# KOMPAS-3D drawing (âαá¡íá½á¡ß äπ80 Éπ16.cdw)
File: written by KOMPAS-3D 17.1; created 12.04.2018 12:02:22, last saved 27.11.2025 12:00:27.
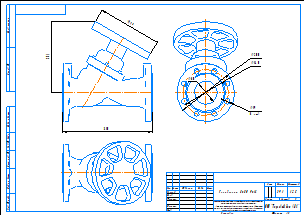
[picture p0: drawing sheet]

Sheet 1: A3, landscape

Title block, sheet 1: name: Гранбаланс Ду80 Ру16; material: Сталь 20  ГОСТ 1050-88; mass: 39,1; sheets: 1; sheet format: A3; stored path: C:\Users\kka\KOMPAS_Work\!Trash\КМ125 КМ127 КМ225Ф Двухходовые клапана\КМ125Ф + PSL\KOMPAS 2D\Гранрег КМ125Ф Ду32 Ру16.cdw

Views: Спереди 1, Спереди, Проекционный вид 2
Referenced files in C:\Users\mipv\Desktop\КБЧ\Имеющиеся\: Гранбаланс Ду80 Ру16  серия 10.m3d
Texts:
  kka
  adl
  Рама для чертежей
  Лит-Масса-Масштаб
  Материал-Предприятие
  Масштаб
  Изм.
  Лист
  № докум.
  Подп.
  Дата
  Лит.
  Разраб.
  Пров.
  Т.контр.
  Листов
  Внимание! Данный продукт является объектом авторского права ООО «Торговый Дом АДЛ».
  Запрещается изменение, копирование, распространение
  (в том числе путем копирования на другие сайты и ресурсы в Интернете)
  или любое иное использование информации и объектов без предварительного
  согласия правообладателя (ООО «Торговый Дом АДЛ»).
  Н.контр.
  Утв.
  ООО "Торговый дом АДЛ"
  Изменение
  Номер документа
  Подпись
  Обозначение документа
  Наименование изделия
  Масса изделия по ГОСТ 2.109-73
  Порядковый номер листа
  Общее количество листов в документе
  Характер работы, выполненной лицом, подписавшим документ
  Наименование или индекс предприятия, выпускающего документ
  Инв. № подл.
  Подп. и дата
  Взам. инв. №
  Инв. № дубл.
  Инвентарный номер подлинника по ГОСТ 2.501-68
  Подпись принявшего подлинник в отдел технической документации
  Инвентарный номер подлинника, взамен которого выпущен данный подлинник
  Инвентарный номер дубликата по ГОСТ 2.502-68
  Подпись принявшего дубликат в отдел технической документации
  Справ. №
  Перв. примен.
  Обозначение документа, взамен или на основании которого выпущен данный документ
  Обозначение документа, в котором впервые записан данный документ
  Подпись лица, копировавшего чертеж
  Обозначение формата листа
  !Рама для чертежа
Dimensions and other numbers on the sheet: 310; 251; 220; 1:2,5; 1; 39,1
